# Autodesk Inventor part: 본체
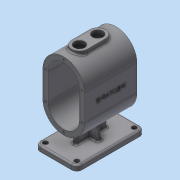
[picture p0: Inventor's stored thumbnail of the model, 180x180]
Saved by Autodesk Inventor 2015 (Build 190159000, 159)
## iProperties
Created: 2016-12
Part Number: 본체
Material: 알루미늄 6061
Document SubType Name: Modeling
Designer: mduedu
Density: 2.71 g/cm^3
Mass: 1171.02 g
Surface Area: 1014.94 cm^2
Volume: 432.112 cm^3
Appearance: 기본값
Author: mduedu
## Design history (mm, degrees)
sketch "스케치1"
  geometry: L1 (40, -25)-(40, 25); L2 (-40, 25)-(-40, -25); L3 (-40, -25)-(40, 25); L4 (40, -25)-(-40, 25); L5 (0, 25)-(0, -25); A1 r 40 centre (0, 25) between (40, 25) and (-40, 25); A2 r 40 centre (0, -25) between (-40, -25) and (40, -25); 1 further point
  constraints: 10 end point, 4 point on circle, 3 tangent, 2 centre point, 2 midpoint, 2 parallel, 1 vertical
  dimensions: "d0" = 130 dimension on A2 A1; "d2" = 80 distance between parallel lines of L1 L2
extrude "돌출1" new body sketch "스케치1" stored distance "d3" = 100; taper "d4" = 0 deg
feature "쉘1" dims "d5" = 10
sketch "스케치2"
  geometry: L1 (-90, 65)-(-100, 65); L2 (-100, 65)-(-100, -65); L3 (-100, -65)-(-90, -65); L4 (-90, -65)-(-90, 65); 2 further points
  constraints: 8 end point, 2 parallel, 1 horizontal, 1 horizontal alignment, 1 midpoint, 1 perpendicular
  dimensions: "d6" = 100 distance from line of L2 point (0, 0); "d7" = 130 distance of L1.end L2.end; "d8" = 10 distance of L2.end L3.end
extrude "돌출2" join sketch "스케치2" stored distance "d9" = 80; taper "d10" = 0 deg
fillet "모깎기1" dims "d11" = 10
sketch "스케치3"
  geometry: L1 (-10, 10)-(-10, 120) reference; L2 (60, 0)-(0, 0) reference; L3 (70, 120)-(70, 10) reference; L4 (0, 130)-(60, 130) reference; A1 r 10 centre (0, 120) between (0, 130) and (-10, 120) reference; A2 r 10 centre (0, 10) between (-10, 10) and (0, 0) reference; A3 r 10 centre (60, 10) between (60, 0) and (70, 10) reference; A4 r 10 centre (60, 120) between (70, 120) and (60, 130) reference; 5 further points
  constraints: 4 coincident
hole "구멍1" sketch "스케치3" at (60, 120), (60, 10), (0, 10), (0, 120) diameter "d12" = 9; stored, may be unused: countersink angle "d16" = 90 deg, drill point angle "d18" = 118 deg; dims "d13" = 6, "d14" = 4, "d15" = 2, "d17" = 8
sketch "스케치5"
  geometry: L1 (34, 35)-(26, 35); L2 (26, 35)-(26, 95); L3 (26, 95)-(34, 95); L4 (34, 95)-(34, 35); L5 (34, 35)-(26, 95); L6 (26, 35)-(34, 95); 1 further point
  constraints: 12 end point, 2 midpoint, 2 parallel, 1 horizontal, 1 perpendicular
  dimensions: "d22" = 8 distance of L2.end L3.end; "d24" = 60 distance of L1.end L2.end
extrude "돌출3" join sketch "스케치5" stored distance "d25" = 80; taper "d26" = 0 deg
feature "면 기울기1" dims angle "d27" = 5 deg
sketch "스케치6"
  geometry: L1 (-30, -90)-(30, -90) reference; L2 (-15.072, -62.052)-(-20, -90); A1 r 40 centre (0, -25) between (-40, -25) and (40, -25) reference; 1 further point
  constraints: 2 end point, 1 point on circle, 1 point on line
  dimensions: "d28" = 20 horizontal distance of A1.centre L2.end; "d29" = 80 deg angle of L2 L1
feature "리브1" sketch "스케치6" dims "d30" = 1, "d31" = 8, "d32" = 0, "d33" = 0, "d34" = 1, "d35" = 1
fillet "모깎기2" dims "d36" = 3
fillet "모깎기3" dims "d37" = 3, "d38" = 3
node "작업 평면1"
sketch "스케치9"
  geometry: 1 further point
sketch "스케치7"
  geometry: L1 (40, 50)-(-40, 50) reference; C1 r 15 at (0, 20); 1 further point
  constraints: 1 centre point, 1 vertical alignment
  dimensions: "d40" = 30 diameter of C1; "d41" = 30 distance from line of C1.centre L1
extrude "돌출4" join sketch "스케치7" stored distance "d42" = 80; taper "d43" = 0 deg
sketch "스케치15"
  geometry: C1 r 15 at (0, -15); C2 r 15 at (0, 20) reference; 1 further point
  constraints: 1 centre point, 1 vertical alignment
  dimensions: "d83" = 30 diameter of C1; "d84" = 35 distance of C1.centre C2.centre
extrude "돌출6" join sketch "스케치15" stored distance "d85" = 10; taper "d86" = 0 deg
hole "구멍2" diameter "d46" = 20; stored, may be unused: countersink angle "d50" = 90 deg, drill point angle "d52" = 118 deg; dims "d44" = 10, "d45" = 10, "d47" = 6, "d48" = 4, "d49" = 2, "d51" = 8
hole "구멍6" diameter "d89" = 20; stored, may be unused: countersink angle "d93" = 90 deg, drill point angle "d95" = 118 deg; dims "d87" = 10, "d88" = 10, "d90" = 6, "d91" = 4, "d92" = 2, "d94" = 8
node "작업 평면2"
sketch "스케치8"
  geometry: C1 r 15 at (0, 0) reference; C2 r 15 at (0, 0); 1 further point
  constraints: 1 centre point, 1 coincident
  dimensions: "d55" = 30 diameter of C2
extrude "돌출5" cut sketch "스케치8" stored distance "d56" = 80; taper "d57" = 0 deg
sketch "스케치16"
  geometry: C1 r 15 at (0, 35); 2 further points
  constraints: 1 centre point, 1 coincident, 1 vertical alignment
  dimensions: "d96" = 30 diameter of C1
extrude "돌출7" cut sketch "스케치16" stored distance "d97" = 10; taper "d98" = 0 deg
sketch "스케치17"
  geometry: L1 (15, 0)-(15, -35); L2 (-15, 0)-(-15, -35); C1 r 10 at (0, 0) reference; C2 r 10 at (0, -35) reference; A1 r 15 centre (0, 0) between (15, 0) and (-15, 0) reference; A2 r 15 centre (0, -35) between (15, -35) and (-15, -35) reference; 1 further point
  constraints: 4 end point, 4 point on circle, 3 tangent, 1 vertical
extrude "돌출8" join sketch "스케치17" stored distance "d99" = 10; taper "d100" = 0 deg
fillet "모깎기5" dims "d101" = 3
chamfer "모따기1" distance "d58" = 1; stored, may be unused: second distance "d59" = 2, angle "d60" = 45 deg
sketch "스케치10"
  geometry: 2 further points
  constraints: 1 coincident, 1 other
feature "엠보싱1" sketch "스케치10" dims "d0" = 130, "d2" = 80, "d11" = 10, "d61" = 0.5, "d62" = 0
sketch "스케치11"
  geometry: 1 further point
hole "구멍3" sketch "스케치11" at (0, 60) diameter "d63" = 3.242; stored, may be unused: countersink angle "d67" = 90 deg, drill point angle "d69" = 120 deg; dims "d64" = 8.6, "d65" = 4, "d66" = 2, "d68" = 10.6
sketch "스케치12"
  geometry: 1 further point
hole "구멍5" sketch "스케치12" at (0, 60) diameter "d70" = 3.242; stored, may be unused: countersink angle "d74" = 90 deg, drill point angle "d76" = 120 deg; dims "d71" = 8.6, "d72" = 4, "d73" = 2, "d75" = 10.6
node "솔리드1"
mirror "대칭1"
pattern_linear "직사각형 패턴1"
pattern_linear "직사각형 패턴2"
node "투영된 루프1"
sketch "스케치13"
  geometry: L1 (-40, 25)-(-40, -25) reference; L2 (40, -25)-(40, 25) reference; L3 (35, 25)-(35, -25); L4 (-35, -25)-(-35, 25); A1 r 40 centre (0, 25) between (40, 25) and (-40, 25) reference; A2 r 40 centre (0, -25) between (-40, -25) and (40, -25) reference; A3 r 35 centre (0, 25) between (35, 25) and (-35, 25); A4 r 35 centre (0, -25) between (-35, -25) and (35, -25); 2 further points
  constraints: 5 point on circle, 4 end point, 2 centre point, 3 other
  dimensions: "d77" = 5 distance between parallel lines of L3 L2
sketch "스케치14"
  geometry: L1 (-40, 25)-(-40, -25) reference; L2 (40, -25)-(40, 25) reference; L3 (35, 25)-(35, -25); L4 (-35, -25)-(-35, 25); A1 r 40 centre (0, 25) between (40, 25) and (-40, 25) reference; A2 r 40 centre (0, -25) between (-40, -25) and (40, -25) reference; A3 r 35 centre (0, 25) between (35, 25) and (-35, 25); A4 r 35 centre (0, -25) between (-35, -25) and (35, -25); 2 further points
  constraints: 5 point on circle, 4 end point, 2 centre point, 3 other
  dimensions: "d80" = 5 distance between parallel lines of L2 L3
node "투영된 루프3"
node "투영된 루프4"
node "투영된 루프5"
